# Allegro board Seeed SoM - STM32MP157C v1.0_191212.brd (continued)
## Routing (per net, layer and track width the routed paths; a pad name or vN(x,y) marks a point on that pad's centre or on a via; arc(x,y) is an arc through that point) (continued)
VDD_CORE: length 25.4
  TOP w0.152: 29.11,27.07 29.28,27.23 U2.5
  TOP w0.203: U3.1D1 U3.1C2 U3.1D3 13.27,12.41 v1(13.39,12.41) 13.73,12.07 U3.1E4 ; U3.1D1 U3.1E2 ; U3.1D1 11.41,12.98 v1(11.41,13.35) ; U3.1C4 v1(13.46,13.52) ; U3.1A2 U3.1B1 11.71,13.97 v1(11.71,14.29) ; U3.1F5 v1(14.13,11.56) ; U3.1F5 U3.1G6 15.11,10.65 v1(15.44,10.33) 15.68,10.09 U3.1H7 ; U3.1F5 U3.1E6 15.4,12.32 15.4,12.41 15.41,12.42 v1(15.41,12.44) 15.57,12.6 U3.1D7 ; U3.1B5 14.38,14.06 14.3,14.14 v1(14.3,14.16) 14.64,14.16 U3.1A6 ; U3.1D5 14.58,12.81 v1(14.58,12.82) 14.85,13.08 14.86,13.08 U3.1C6 ; v1(15.98,11.65) 15.98,11.6 U3.1F7 ; U3.1B3 v1(13.49,14.31) U3.1A4
  BOTTOM w0.203: C29.1 15.65,10.18 15.5,10.33 v1(15.44,10.33) ; v1(14.13,11.56) 14.13,11.59 C31.1 ; C28.1 11.49,13.24 11.43,13.3 11.43,13.32 v1(11.41,13.35) 11.43,13.37 11.43,13.4 11.46,13.43 11.46,13.47 11.48,13.49 C30.1 11.48,14.09 11.68,14.29 v1(11.71,14.29)
  BOTTOM w0.254: 13.97,13.85 C33.1 ; v1(13.39,12.41) 13.74,12.07 C31.1 ; 13.8,13.86 v1(13.46,13.52)
  BOTTOM w0.305: C33.1 13.52,14.31 v1(13.49,14.31) 13.08,13.91 C32.1 13.13,13.85 v1(13.46,13.52) ; C33.1 14,13.86 v1(14.3,14.16) ; C33.1 13.8,13.86 ; v1(15.98,11.65) 16.02,11.69 C120.1 15.95,12 15.83,12 15.81,11.98 15.49,11.98
  BOTTOM w0.381: v1(14.58,12.82) 14.86,13.09 C34.1 14.98,13.03 14.98,12.81 15.25,12.54 15.31,12.54 v1(15.41,12.44) 15.28,12.31 C35.1 15.49,11.98 15.83,11.65 v1(15.98,11.65) ; C121.1 14.8,14.66 v1(14.3,14.16)
  vias: v1(27.97,26.31) v1(27.97,25.94) v1(28.48,26.31) v1(28.48,25.92)
VDD_USB: length 20.2
  TOP w0.089: U3.AA17 16.63,7.21 16.13,7.21 U3.AA15 v2(15.88,7.46)
  TOP w0.152: 25.81,30.12 26.14,30.44 U2.39
  TOP w0.381: 25.81,30.12 25.81,29.86 v1(25.23,29.28) C207.1
  GND02 w0.254: v1(16.59,4.36) 15.88,5.07 v2(15.88,7.46)
  LAYER_3 w0.356: v1(25.79,3.83) 25.79,3.14 25.2,2.56 22.89,2.56 20.25,5.2 17.43,5.2 v1(16.59,4.36)
  BOTTOM w0.254: v1(16.59,4.36) 16.97,3.98 C52.1
VDDA: length 34.8
  TOP w0.203: 33.66,31.32 33.59,31.24 U2.20
  TOP w0.356: v1(35.95,31.79) 34.98,31.79 34.73,31.54 C206.1
  TOP w0.381: C206.1 34.24,31.21 34.13,31.32 33.66,31.32
  LAYER_3 w0.356: v1(16.92,1.32) 17.59,0.65 v1(25.43,0.65)
  LAYER_5 w0.356: 27.97,5.6 27.97,3.19 v1(25.43,0.65) ; v1(16.92,1.32) 16.26,1.32 15.84,1.74 15.84,1.86 15.3,2.4 v1(10.8,2.4) ; 34.07,23.26 34.07,29.23 35.95,31.11 v1(35.95,31.79)
  BOTTOM w0.381: v1(10.8,2.4) 10.8,2.61 R93.1
VDDQ_DDR: length 56.8
  TOP w0.152: 31.14,26.94 30.87,27.21 U2.9
  TOP w0.203: U3.1G8 16.58,10.65 v1(16.6,10.63) ; U3.1H9 U3.1J8 16.33,9.08 v1(16.26,9.01) ; U3.1E8 16.69,11.6 v1(16.69,11.56) 16.95,11.3 U3.1F9 ; U3.1D9 U3.1C8 U3.1B9 16.98,14.05 v1(16.82,14.21) 16.48,14.55 U3.1A8 v1(15.96,14.18) U3.1B7
  TOP w0.305: U6.R1 v3(24.3,15.4) ; U6.R9 v3(24.27,8.23)
  TOP w0.356: v3(28.27,9.03) U6.K8 ; v3(36.28,9.03) U6.A8 ; v3(25.87,8.23) U6.N9 ; v3(32.28,15.43) U6.F1 ; v3(33.88,14.63) U6.D2 ; v3(35.48,14.63) U6.B2 ; v3(25.87,15.43) U6.N1 ; v3(33.08,8.23) U6.E9 ; U6.A1 36.07,15.22 36.07,15.72 v3(35.54,16.25) ; v3(31.48,9.82) U6.G7 ; v3(34.68,15.43) U6.C1 ; v3(30.68,14.63) U6.H2 ; v3(28.27,14.63) U6.K2 ; v3(30.68,8.23) U6.H9 ; v3(33.88,8.23) U6.D9 ; v3(34.68,8.23) U6.C9
  TOP w0.381: R102.2 v1(25.15,17.97) C80.1 ; C148.1 28.86,5.78 v1(29.01,5.93) ; v1(35.74,5.96) 35.72,5.93 C153.1 C152.1 ; C157.1 C156.1 ; C156.1 34.45,17.62 34.68,17.39 v1(34.68,17.29) ; C156.1 C155.1 ; C152.1 v1(34.7,5.93) ; C152.1 C151.1 C150.1 v1(32.31,5.52) C149.1 ; v1(24.45,5.52) C81.1 C147.1 v1(25.94,5.91) ; C155.1 v1(35.46,17.36) ; C155.1 C154.1 ; C82.1 v1(28.86,17.43)
  BOTTOM w0.203: C44.1 16.6,10.46 v1(16.6,10.63) 16.77,10.8 C42.1 16.77,11.48 v1(16.69,11.56) ; v1(16.82,14.21) 16.82,14.05 C43.1 16.37,13.77 v1(15.96,14.18) 16.26,14.18 16.3,14.21 v1(16.82,14.21)
  BOTTOM w0.381: v1(34.75,6.57) C79.1 v1(35.74,5.96) ; v1(27.13,3.83) 27.13,2.89 26.52,2.28 22.43,2.28 20.65,4.05 20.65,6.04 19.05,7.64 C132.1 C45.1 16.42,8.85 v1(16.26,9.01) ; v1(34.68,17.29) 34.68,17.92 34.95,18.19 C162.1 35.64,17.54 v1(35.46,17.36)
  vias: v1(31.58,24.07) v1(31.6,23.69) v1(32.01,24.14) v1(32.01,23.71) v1(34.57,26.43) v1(34.95,26.43)
ADC1_INN1: length 41.6
  TOP w0.089: U3.U3 10.13,9.21 10.58,9.21 v1(10.76,9.03)
  LAYER_5 w0.102: v1(14.25,36.59) 14.15,36.69 14.15,37.07 13.8,37.43 7.07,37.43 6.25,36.62 6.25,24.58 6.56,24.27 6.56,19.7 7.17,19.09 7.17,18.63 6.61,18.08 6.61,16.45 8.28,14.77 8.28,12.34 9.17,11.45 9.17,9.9 10.04,9.04 10.43,9.08 10.53,9 v1(10.76,9.03)
  BOTTOM w0.095: J4.37 14.22,35.76 14.16,35.82 14.16,36.5 v1(14.25,36.59)
ADC1_INP1: length 41.6
  TOP w0.089: v1(10.7,9.51) 10.67,9.51 10.61,9.45 U3.U4
  LAYER_5 w0.102: v1(13.72,36.57) 13.85,36.69 13.85,36.95 13.67,37.13 7.19,37.13 6.56,36.49 6.56,35.55 6.66,35.45 6.94,35.45 7.04,35.35 7.04,35.14 6.94,35.04 6.66,35.04 6.56,34.94 6.56,34.74 6.66,34.64 6.94,34.64 7.04,34.53 7.04,34.33 6.94,34.23 6.66,34.23 6.56,34.13 6.56,33.9 6.66,33.8 6.94,33.8 7.04,33.7 7.04,33.5 6.94,33.39 6.66,33.39 6.56,33.29 6.56,24.7 6.86,24.4 6.86,19.83 7.47,19.22 7.47,18.51 6.91,17.95 6.91,16.58 8.59,14.9 8.59,12.46 9.48,11.57 9.48,10.03 10.15,9.36 10.39,9.38 10.48,9.49 v1(10.7,9.51)
  BOTTOM w0.095: v1(13.72,36.57) 13.77,36.57 13.88,36.46 13.88,35.82 13.82,35.76 J4.39
ADC2_INP2: length 43.8
  TOP w0.089: U3.Y5 10.79,8.05 10.79,8.13 v1(10.7,8.22)
  LAYER_3 w0.089: v1(15.24,37.05) 12.96,37.05 12.78,37.22 6.83,37.22 6.81,37.2 5.92,37.2 v1(5.21,36.49)
  LAYER_5 w0.089: v1(10.7,8.22) 10.45,8.22 10.41,8.26 9.97,8.26 8.77,9.46 8.77,11.27 8.01,12.03 8.01,14.65 6.32,16.34 6.32,17.77 5.8,18.29 5.8,22.52 5.29,23.03 5.29,26.46 4.83,26.91 4.83,31.92 5.21,32.3 v1(5.21,36.49)
  BOTTOM w0.089: J4.33 15.02,36.03 15.04,36.05 15.04,36.76 15.07,36.8 15.07,36.87 v1(15.24,37.05)
AUDIO_RST: length 25.8
  TOP w0.089: U3.Y13 14.88,8.18 14.76,8.3 14.76,8.37 14.76,8.37 14.76,8.55 v1(14.51,8.8)
  LAYER_3 w0.089: v1(12.18,22.95) 12.44,22.69 13.17,22.69 14.03,21.83 14.86,21.83 17.25,19.44 17.25,19.37 v1(17.43,19.19)
  LAYER_5 w0.089: v1(17.43,19.19) 18.06,18.56 18.06,17.62 19.03,16.65 19.03,9.39 18.75,9.11 18.75,8.43 18.11,7.79 15.22,7.79 14.76,8.25 14.76,8.38 14.76,8.38 14.76,8.55 v1(14.51,8.8)
  BOTTOM w0.089: J2.23 12.23,22.65 12.18,22.7 v1(12.18,22.95)
BOOT0: length 19.1
  TOP w0.089: v1(8.11,11.45) U3.N1
  LAYER_5 w0.089: v1(4.53,21.77) 4.83,21.47 4.83,16.73 4.47,16.37 4.47,12.97 5.9,11.54 6.44,11.54 6.66,11.32 7.28,11.32 7.42,11.45 v1(8.11,11.45)
  BOTTOM w0.089: J2.5 8.63,21.27 8.46,21.1 5.2,21.1 v1(4.53,21.77)
BOOT1: length 16.7
  TOP w0.089: U3.N4 10.53,11.6 10.75,11.6 v1(10.81,11.53)
  LAYER_3 w0.089: v1(7.73,23.59) 8.7,22.61 8.7,22.54 v1(8.88,22.37)
  LAYER_5 w0.089: v1(7.73,23.59) 8.18,23.13 8.18,21.48 7.75,21.04 7.75,20.64 8.21,20.18 8.21,19.83 8.89,19.14 8.89,17.88 9.35,17.42 9.35,13.17 10.64,11.89 10.64,11.71 v1(10.81,11.53)
  BOTTOM w0.089: J2.7 9.03,22.18 8.88,22.34 v1(8.88,22.37)
BOOT2: length 21.8
  TOP w0.089: U3.M2 7.7,11.95 7.64,11.89 v1(7.61,11.89)
  LAYER_3 w0.089: v1(9.78,23) 8.87,23.92 6.09,23.92 5.86,23.69 5.24,23.69 5.15,23.78 v1(4.9,23.78)
  LAYER_5 w0.089: v1(7.61,11.89) 7.8,12.09 7.8,14.57 5.59,16.78 5.59,22.34 4.9,23.03 v1(4.9,23.78)
  BOTTOM w0.089: v1(9.78,23) 9.61,22.83 9.61,22.8 9.43,22.62 J2.9
BST_OUT: length 4.5
  TOP w0.152: v1(27.33,33.04) 27.59,33.04 27.68,32.95 U2.34 27.68,32.61 27.59,32.53
  TOP w0.381: R150.1 23.85,31.08 v1(23.65,30.88)
  BOTTOM w0.203: J4.21 v1(17.42,36.33) ; J4.17 18.22,36.05 v1(17.94,36.34) 17.94,36.03 17.82,35.92 J4.19
  vias: v1(23.65,31.26) v1(26.95,33.04)
DDR_A0: length 13.4
  TOP w0.089: U3.L20 18.02,12.45 v1(17.94,12.53)
  TOP w0.127: v3(25.87,13.83) U6.N3
  BOTTOM w0.127: R17.1 26.58,15.86 26.27,15.55 26.27,15.26 25.87,14.86 v3(25.87,13.83) 25.65,13.6 25.65,13.44 24.62,12.41 22.74,12.41 21.34,13.81 20.63,13.81 19.28,12.46 18.27,12.46 18.21,12.53 v1(17.94,12.53)
DDR_A1: length 13.1
  TOP w0.089: U3.P22 19.63,10.71 20.75,10.71
  TOP w0.127: v1(25.07,9.83) U6.P7 25.12,10.58 23.09,10.58 22.97,10.46 22.97,9.08 22.84,8.96 22.59,8.96 22.46,9.08 22.46,10.58 22.33,10.71 20.75,10.71
  BOTTOM w0.127: R18.1 26.32,8.06 26.3,8.07 26.3,8.44 26.12,8.63 25.71,8.63 25.51,8.83 25.51,9.39 v1(25.07,9.83)
DDR_A2: length 12
  TOP w0.089: U3.J20 18.12,13.45 18.11,13.45 18.06,13.45 v1(18.06,13.45)
  TOP w0.127: v3(25.07,13.83) U6.P3
  BOTTOM w0.089: 18.32,13.71 v1(18.06,13.45)
  BOTTOM w0.127: R19.1 25.68,15.76 25.48,15.55 25.48,14.23 v3(25.07,13.83) 25.07,13.27 24.52,12.72 22.84,12.72 21.52,14.04 18.65,14.04 18.32,13.71
DDR_A3: length 13.5
  TOP w0.089: U3.K22 19.7,13.27 20.98,13.27 v1(21.19,13.48)
  TOP w0.127: U6.N2 26.64,13.86 v3(26.67,13.86)
  BOTTOM w0.127: R20.1 27.48,16.14 27.11,15.77 27.11,15.28 26.88,15.06 26.59,15.06 26.31,14.78 26.31,14.23 v3(26.67,13.86) 26.27,13.46 26.27,13.28 26.33,13.22 26.33,13.04 26.15,12.86 25.98,12.86 25.86,12.97 25.66,12.97 25.49,12.8 25.49,12.62 25.62,12.5 25.62,12.32 25.44,12.14 25.15,12.14 25.09,12.2 24.91,12.2 24.77,12.06 22.61,12.06 v1(21.19,13.48)
DDR_A4: length 11.6
  TOP w0.089: v1(17.33,8.8) 17.58,8.8 17.59,8.8 17.62,8.8 17.77,8.95 U3.V20
  TOP w0.127: v3(25.07,9.03) U6.P8
  LAYER_3 w0.089: v1(17.33,8.8) 17.53,8.6 17.53,8.58 17.82,8.3 18.17,8.3
  LAYER_3 w0.127: 18.17,8.3 22.13,8.3 22.48,8.65 24.7,8.65 v3(25.07,9.03)
  BOTTOM w0.127: v3(25.07,9.03) 25.07,8.8 25.44,8.44 25.44,7.81 25.43,7.79 R21.1
DDR_A5: length 13.5
  TOP w0.089: U3.H20 17.5,13.95 17.22,13.68 v1(17.22,13.61)
  TOP w0.127: v3(25.07,14.63) U6.P2
  BOTTOM w0.089: 18.17,14.11 18.09,14.04 17.65,14.04 17.56,13.94 17.53,13.94 17.35,13.76 17.35,13.73 v1(17.22,13.61)
  BOTTOM w0.127: 18.17,14.11 18.39,14.34 21.72,14.34 23.04,13.02 24.34,13.02 24.69,13.38 24.69,14.25 v3(25.07,14.63) 24.71,15 24.71,15.77 24.79,15.86 R22.1
DDR_A6: length 10.7
  TOP w0.089: v1(17.99,8.63) 18.21,8.63 U3.W20
  TOP w0.127: v3(24.27,9.03) U6.R8
  LAYER_3 w0.127: v3(24.27,9.03) 23.96,9.03 23.89,8.96 22.19,8.96 21.99,8.75 21.68,8.75 21.48,8.96 21.25,8.96 21.12,8.83 21.12,8.73 20.99,8.6 20.74,8.6 20.61,8.73 20.61,8.83 20.49,8.96 20.23,8.96 20.1,8.83 20.1,8.73 19.98,8.6 19.72,8.6 19.6,8.73 19.6,8.83 19.47,8.96 19.22,8.96 19.09,8.83 19.09,8.73 18.96,8.6 18.71,8.6 18.58,8.73 18.58,8.83 18.45,8.96 18.27,8.96 18.18,8.87 18.18,8.82 v1(17.99,8.63)
  BOTTOM w0.127: v3(24.27,9.03) 23.88,8.64 23.88,7.68 23.71,7.51 R23.1
DDR_A7: length 12
  TOP w0.089: U3.E20 18.14,15.45 18.09,15.41 18.07,15.41 v1(18.07,15.4)
  TOP w0.127: v3(24.27,14.63) U6.R2
  LAYER_3 w0.127: v3(24.27,14.63) 23.54,14.63 22.05,16.12 22.05,17.05 v1(22.42,17.42)
  BOTTOM w0.127: v3(24.27,14.63) 23.91,15 R24.1 ; v1(18.07,15.4) 19.43,15.4 21.44,17.42 v1(22.42,17.42)
DDR_A8: length 11.2
  TOP w0.089: v1(17.33,8.35) 17.63,8.35 17.7,8.27 18.06,8.27 U3.Y20
  TOP w0.127: U6.T8 23.01,8.57 23.01,8.42 v3(22.79,8.19)
  LAYER_3 w0.127: v3(22.79,8.19) 22.25,7.66 21.42,7.66 21.29,7.79 21.29,7.89 21.17,8.02 20.91,8.02 20.79,7.89 20.79,7.69 20.66,7.56 20.41,7.56 20.28,7.69 20.28,7.89 20.15,8.02 19.92,8.02 19.8,7.89 19.8,7.66 19.67,7.53 19.41,7.53 19.29,7.66 19.29,7.86 19.14,8.02 18.88,8.02 18.75,7.89 18.75,7.79 18.63,7.66 18.01,7.66 v1(17.33,8.35)
  BOTTOM w0.127: R25.1 22.76,7.79 22.79,7.82 v3(22.79,8.19)
DDR_A9: length 11.8
  TOP w0.127: v1(18.04,14.57) 18.16,14.45 U3.G20 ; v3(24.27,13.83) U6.R3
  BOTTOM w0.127: v1(18.04,14.57) 18.04,14.6 18.22,14.77 19.82,14.77 20.05,15 22.2,15 22.99,14.21 22.99,13.55 23.27,13.27 24.04,13.27 24.27,13.51 v3(24.27,13.83) 23.91,14.2 23.91,14.47 22.97,15.41 R26.1
DDR_A10: length 13.9
  TOP w0.089: 20.83,10.45 U3.R22
  TOP w0.127: v1(22,9.9) 21.44,10.45 20.83,10.45 ; v3(27.47,9.83) U6.L7
  LAYER_3 w0.127: v1(22,9.9) 22.48,9.9 23.19,10.61 26.69,10.61 v3(27.47,9.83)
  BOTTOM w0.127: v3(27.47,9.83) 29.34,9.83 29.8,9.36 29.8,8.03 29.87,7.96 R27.1
DDR_A11: length 11.8
  TOP w0.089: U3.R20 18.18,10.25 17.78,10.25 17.7,10.17 17.7,10.09 v1(17.53,9.92)
  TOP w0.127: v3(24.27,9.83) U6.R7
  LAYER_3 w0.127: v1(17.53,9.92) 17.86,10.25 18.8,10.25 19.49,9.57 22.61,9.57 23.27,10.23 23.87,10.23 v3(24.27,9.83)
  BOTTOM w0.127: v3(24.27,9.83) 24.69,9.41 24.69,7.94 24.54,7.79 R28.1
DDR_A12: length 12.9
  TOP w0.089: U3.P23 20.87,10.95
  TOP w0.127: v1(25.89,9.84) U6.N7 25.91,10.59 25.91,11.15 25.82,11.24 25.57,11.24 25.48,11.15 25.48,11.01 25.3,10.84 24.69,10.84 24.41,11.12 24.12,11.12 23.91,10.9 23.46,10.9 23.12,11.24 22.86,11.24 22.58,10.95 20.87,10.95
  BOTTOM w0.127: v1(25.89,9.84) 26.29,9.44 26.83,9.44 27.66,8.6 28.43,8.6 28.6,8.42 28.6,7.96 28.16,7.51 R29.1
DDR_A13: length 9.2
  TOP w0.089: v1(17.66,14.88) 17.74,14.95 U3.F20
  TOP w0.127: v3(23.47,13.83) U6.T3
  BOTTOM w0.127: v1(17.66,14.88) 17.85,15.06 19.62,15.06 20.71,16.15 21.66,16.15 21.66,16.14 R30.1 22.06,16.14 22.64,15.57 22.64,15.33 23.47,14.49 v3(23.47,13.83)
DDR_A14: length 11.1
  TOP w0.089: U3.R21 18.63,10.71 18.24,10.71 18.01,10.48 17.83,10.48 17.79,10.52 17.63,10.52 v1(17.46,10.7)
  TOP w0.127: v3(23.47,9.83) U6.T7
  BOTTOM w0.089: v1(17.46,10.7) 17.51,10.65 17.51,10.57 17.59,10.48 18.45,10.48
  BOTTOM w0.127: v3(23.47,9.83) 22.38,8.73 22.38,7.96 21.94,7.51 R31.1 21.81,7.51 18.84,10.48 18.45,10.48
DDR_A15: length 15.3
  TOP w0.089: v1(17.92,10.83) 17.95,10.86 18.09,10.86 18.18,10.95 U3.P20
  TOP w0.127: U6.M7 v1(26.67,9.82)
  BOTTOM w0.127: R119.1 29.05,7.51 29.49,7.96 29.49,9.24 29.29,9.44 27.32,9.44 26.93,9.82 v1(26.67,9.82) 26.24,10.25 19.59,10.25 19.01,10.83 18.19,10.83 v1(17.92,10.83)
DDR_BA0: length 12.9
  TOP w0.089: U3.L23 20.29,12.45 20.5,12.67 20.81,12.67 v1(20.92,12.78)
  TOP w0.127: v3(26.67,14.63) U6.M2
  BOTTOM w0.127: R32.1 28.42,16.14 27.13,14.85 26.9,14.85 v3(26.67,14.63) 27.04,14.26 27.04,13.35 25.4,11.7 22.48,11.7 21.39,12.79 21.1,12.79 21.09,12.78 v1(20.92,12.78)
DDR_BA1: length 12
  TOP w0.089: v1(17.99,9.3) 18.23,9.3 U3.U20
  TOP w0.127: v3(25.87,9.03) U6.N8
  LAYER_3 w0.127: v1(17.99,9.3) 24.03,9.3 24.19,9.46 25.44,9.46 v3(25.87,9.03)
  BOTTOM w0.127: v3(25.87,9.03) 26.19,9.03 26.57,8.65 27.13,8.65 27.44,8.34 27.44,7.68 27.27,7.51 R33.1
DDR_BA2: length 23.9
  TOP w0.089: v1(17.47,11.58) 17.65,11.75 17.73,11.75 17.78,11.81 18.04,11.81 18.14,11.71 18.63,11.71 U3.M21
  TOP w0.127: U6.M3 27.07,12.73 27.24,12.56 27.79,12.56 28.24,13.01 v3(29.09,13.01)
  LAYER_3 w0.127: v3(29.09,13.01) 28.77,13.01 27.41,11.65 20.45,11.65 20.2,11.9 17.8,11.9 v1(17.47,11.58)
  BOTTOM w0.127: R34.1 33.88,16.14 33.48,15.75 33.48,14.44 32.05,13.01 v3(29.09,13.01)
DDR_CASN: length 19
  TOP w0.089: v1(17.91,11.5) 17.95,11.45 U3.N20
  TOP w0.127: v3(28.27,13.83) U6.K3
  BOTTOM w0.127: v1(17.91,11.5) 19.18,11.5 19.87,10.81 26.04,10.81 28.27,13.05 v3(28.27,13.83) 28.5,13.83 28.93,14.26 31.67,14.26 31.86,14.44 31.86,15.6 32.11,15.86 R36.1
DDR_CKE: length 20.1
  TOP w0.089: v1(18.02,9.92) 18.09,9.92 18.12,9.95 U3.T20
  TOP w0.127: R14.2 R38.1 29.87,5.99 28.25,7.61 v1(28.25,8.2) U6.K9
  LAYER_3 w0.127: v1(28.25,8.2) 27.86,8.59 25.72,8.59 25.51,8.38 25.51,7.89 25.3,7.69 22.94,7.69 22.33,7.08 v1(22.33,5.88)
  BOTTOM w0.127: v1(18.02,9.92) 18.85,9.92 21.26,7.51 21.26,6.44 21.82,5.88 v1(22.33,5.88)
DDR_CLK: length 32.9
  TOP w0.089: 21.49,12.06 21.14,11.7 19.63,11.7 U3.N22
  TOP w0.095: U6.J7 29.21,10.49 29.21,10.67 29.36,10.82 33.94,10.82 34.2,11.08 34.2,11.69 33.94,11.95 33.28,11.95 33.18,12.04 33.18,12.3 32.92,12.56 32.5,12.56 32.24,12.3 32.24,12.04 32.15,11.95 30.66,11.95 30.54,12.07 30.54,12.81 30.24,13.1 29.78,13.1 29.47,12.79 29.47,12.3 29.38,12.21 28.69,12.21 28.35,11.86 28.35,11.21 28.25,11.12 28.06,11.12 27.96,11.21 27.96,11.75 27.71,12 27.28,12 27.02,11.75 27.02,11.21 26.93,11.12 26.69,11.12 26.59,11.21 26.59,12.66 26.26,13 25.49,13 25.23,12.73 25.23,11.89 25.1,11.76 24.87,11.76 24.78,11.86 24.78,12.74 24.52,13 24.1,13 23.84,12.74 23.84,11.86 23.74,11.76 23.55,11.76 23.46,11.86 23.46,12.79 23.2,13.05 22.78,13.05 22.52,12.79 22.52,11.96 22.42,11.87 22.06,11.87 21.85,12.08 R16.2 21.52,12.08 21.49,12.06
DDR_CLKN: length 32.9
  TOP w0.089: 21.57,11.34 21.39,11.52 21.25,11.52 21.16,11.44 21.16,11.36 21.07,11.27 20.95,11.27 20.86,11.36 20.86,11.43 20.77,11.52 20.64,11.52 20.55,11.43 20.55,11.33 20.49,11.27 20.32,11.27 20.25,11.34 20.25,11.44 20.16,11.52 19.95,11.52 U3.N23
  TOP w0.095: 21.57,11.34 21.6,11.32 R16.1 21.9,11.32 22.17,11.59 22.54,11.59 22.8,11.84 22.8,12.67 22.89,12.77 23.08,12.77 23.18,12.67 23.18,11.74 23.44,11.48 23.86,11.48 24.12,11.74 24.12,12.62 24.21,12.72 24.4,12.72 24.5,12.62 24.5,11.74 24.76,11.48 25.21,11.48 25.51,11.78 25.51,12.61 25.61,12.72 26.14,12.72 26.31,12.54 26.31,11.1 26.57,10.84 27.04,10.84 27.3,11.1 27.3,11.63 27.4,11.73 27.59,11.73 27.68,11.63 27.68,11.1 27.94,10.84 28.37,10.84 28.62,11.1 28.62,11.74 28.81,11.93 29.49,11.93 29.75,12.19 29.75,12.67 29.9,12.82 30.13,12.82 30.26,12.69 30.26,11.95 30.54,11.67 32.26,11.67 32.52,11.93 32.52,12.19 32.62,12.28 32.81,12.28 32.9,12.19 32.9,11.93 33.16,11.67 33.83,11.67 33.92,11.57 33.92,11.19 33.83,11.1 29.94,11.1 29.85,11.19 29.85,11.34 29.75,11.45 29.52,11.45 29.42,11.34 29.42,11.17 29.34,11.1 29.24,11.1 28.94,10.79 28.94,10.49 U6.K7
DDR_CSN: length 14.9
  TOP w0.089: U3.M22 19.57,11.95 19.59,11.93 20.68,11.93 20.83,12.08 v1(21.01,12.08)
  TOP w0.127: v3(27.47,14.63) U6.L2
  BOTTOM w0.127: v1(21.01,12.08) 21.59,12.08 22.28,11.4 25.63,11.4 27.06,12.82 27.06,13.06 27.12,13.13 27.12,13.14 27.47,13.49 v3(27.47,14.63) 27.91,15.06 28.59,15.06 29.09,15.56 30.1,15.56 30.34,15.79 R37.1
DDR_D0: length 40
  TOP w0.089: U3.E22 19.63,15.21 20.1,15.21 20.73,15.84
  TOP w0.127: v1(34.5,21.15) 35.69,21.15 36.83,20.01 36.83,14.49 36.57,14.23 U6.A2 ; v1(21.7,20.44) 20.98,20.44 20.73,20.18 20.73,15.84
  LAYER_3 w0.127: v1(34.5,21.15) 33.91,21.73 33.44,21.73 33.31,21.61 33.31,21.35 33.19,21.23 32.93,21.23 32.81,21.35 32.81,21.61 32.68,21.73 31.5,21.73 31.37,21.61 31.37,21.15 31.24,21.02 30.99,21.02 30.86,21.15 30.86,21.61 30.74,21.73 30.48,21.73 30.36,21.61 30.36,21.15 30.23,21.02 29.97,21.02 29.85,21.15 29.85,21.61 29.72,21.73 29.47,21.73 29.34,21.61 29.34,21.15 29.21,21.02 28.96,21.02 28.83,21.15 28.83,21.61 28.7,21.73 28.45,21.73 28.32,21.61 28.32,21.15 28.2,21.02 27.94,21.02 27.82,21.15 27.82,21.61 27.69,21.73 27.43,21.73 27.31,21.61 27.31,21.15 27.18,21.02 26.93,21.02 26.8,21.15 26.8,21.61 26.67,21.73 26.42,21.73 26.29,21.61 26.29,21.15 26.16,21.02 25.91,21.02 25.78,21.15 25.78,21.61 25.66,21.73 25.4,21.73 25.28,21.61 25.28,21.15 25.15,21.02 24.89,21.02 24.77,21.15 24.77,21.61 24.64,21.73 24.39,21.73 24.26,21.61 24.26,21.15 24.13,21.02 23.88,21.02 23.75,21.15 23.75,21.61 23.62,21.73 22.72,21.73 21.7,20.7 v1(21.7,20.44)
DDR_D1: length 39.9
  TOP w0.089: U3.F22 20.2,14.95 21.09,15.84
  TOP w0.127: v3(34.68,13.83) U6.C3 ; 21.09,15.84 21.09,19.88 21.11,19.9 v1(21.11,20.01)
  LAYER_3 w0.127: v3(34.68,13.83) 35.09,14.24 35.69,14.24 35.92,14.47 35.92,18.19 34.51,19.6 29.85,19.6 29.72,19.73 29.72,20.49 29.62,20.59 29.33,20.59 29.2,20.46 29.2,19.78 29.07,19.65 28.82,19.65 28.69,19.78 28.69,20.46 28.57,20.59 28.31,20.59 28.18,20.46 28.18,19.78 28.06,19.65 27.8,19.65 27.68,19.78 27.68,20.46 27.55,20.59 27.26,20.59 27.13,20.46 27.13,19.78 26.98,19.62 26.76,19.62 26.63,19.75 26.63,20.5 26.5,20.63 26.25,20.63 26.12,20.5 26.12,19.76 25.99,19.62 25.74,19.62 25.61,19.75 25.61,20.49 25.49,20.62 25.23,20.62 25.11,20.49 25.11,19.75 24.98,19.62 24.73,19.62 24.6,19.75 24.6,20.41 24.47,20.54 24.03,20.54 23.9,20.41 23.9,19.52 23.78,19.4 23.52,19.4 23.4,19.52 23.4,20.41 23.27,20.54 22.61,20.54 22.48,20.41 22.48,19.52 22.33,19.37 22.03,19.37 21.9,19.5 21.9,19.88 21.77,20.01 v1(21.11,20.01)
DDR_D2: length 39.7
  TOP w0.089: U3.H21 18.63,14.2 17.73,14.2 v1(17.59,14.34)
  TOP w0.127: v3(36.36,10.71) U6.A7
  LAYER_3 w0.127: v1(17.59,14.34) 17.78,14.15 18.08,14.15 18.17,14.24 18.18,14.24 19.33,15.4 19.33,19.36 22.47,22.5 34.8,22.5 37.39,19.9 37.39,12.19 37.27,12.06 36.96,12.06 36.83,11.93 36.83,11.68 36.96,11.55 37.27,11.55 37.39,11.42 37.39,11.04 37.06,10.71 v3(36.36,10.71)
DDR_D3: length 39.9
  TOP w0.089: U3.E21 19.13,15.7 20.11,15.7
  TOP w0.127: v3(34.68,14.63) U6.C2 ; v1(20.25,17.21) 20.25,15.84 20.11,15.7
  LAYER_3 w0.127: v3(34.68,14.63) 35.08,15.03 35.08,16.07 34.95,16.2 34.32,16.2 34.19,16.32 34.19,16.65 34.29,16.75 34.85,16.75 35.06,16.96 35.06,18.51 34.88,18.69 34.55,18.69 34.42,18.56 34.42,17.5 34.21,17.29 33.74,17.29 33.56,17.47 33.56,18.79 33.1,19.24 31.06,19.24 30.93,19.12 30.93,18.89 30.8,18.76 30.55,18.76 30.42,18.89 30.42,19.12 30.29,19.24 29.98,19.24 29.8,19.07 29.8,18.86 29.67,18.74 28.68,18.74 28.53,18.89 28.53,19.02 28.38,19.17 27.84,19.17 27.69,19.02 27.69,18.81 27.56,18.69 25.27,18.69 24.99,18.96 21.72,18.96 21.54,18.78 21.54,15.05 21.41,14.93 21.16,14.93 21.03,15.05 21.03,15.28 20.88,15.43 20.2,15.43 20.07,15.56 20.07,15.81 20.2,15.94 20.9,15.94 21.03,16.07 21.03,16.3 20.9,16.42 20.65,16.42 20.53,16.55 20.53,16.81 20.65,16.93 20.9,16.93 21.03,17.06 21.03,18.81 20.9,18.94 20.54,18.94 20.25,18.65 v1(20.25,17.21)
DDR_D4: length 39.9
  TOP w0.089: U3.J21 18.63,13.7 18.25,13.7 18.19,13.76 17.73,13.76 17.61,13.65 v1(17.61,13.4)
  TOP w0.127: v3(35.48,9.03) U6.B8
  LAYER_3 w0.127: v1(17.61,13.4) 17.61,13.67 17.86,13.91 18.27,13.91 19.69,15.33 19.69,19.19 22.61,22.11 34.47,22.11 36.99,19.6 36.99,12.72 35.87,11.6 35.87,9.42 v3(35.48,9.03)
DDR_D5: length 40
  TOP w0.089: U3.J22 20.68,13.45 21.34,14.11
  TOP w0.127: 21.34,14.11 22.25,14.11 22.94,14.8 22.94,15.41 22.48,15.87 v1(22.48,16.45) ; v3(34.68,9.03) U6.C8
  LAYER_3 w0.127: v3(34.68,9.03) 34.31,9.39 34.31,10.83 34.18,10.96 33.23,10.96 33.1,11.09 33.1,11.34 33.23,11.47 34.18,11.47 34.31,11.59 34.31,11.85 34.18,11.97 33.23,11.97 33.1,12.1 33.1,12.36 33.23,12.48 34.18,12.48 34.31,12.61 34.31,15.65 33.14,16.82 33.14,17.07 33.01,17.2 32.75,17.2 32.62,17.32 32.62,17.58 32.75,17.7 33.01,17.7 33.14,17.83 33.14,18.11 32.87,18.38 32.48,18.38 32.35,18.51 32.35,18.81 32.22,18.94 31.97,18.94 31.84,18.81 31.84,18.51 31.72,18.38 31.25,18.38 31.13,18.25 31.13,18.1 31,17.97 30.75,17.97 30.62,18.1 30.62,18.25 30.49,18.38 30.24,18.38 30.11,18.25 30.11,18.1 29.98,17.97 29.73,17.97 29.6,18.1 29.6,18.25 29.48,18.38 29.22,18.38 29.1,18.25 29.1,18.1 28.97,17.97 28.71,17.97 28.59,18.1 28.59,18.25 28.46,18.38 26.47,18.38 26.35,18.25 26.35,17.54 26.22,17.42 25.97,17.42 25.84,17.54 25.84,18.25 25.71,18.38 24.82,18.38 24.7,18.25 24.7,18.08 24.57,17.95 24.31,17.95 24.16,18.1 24.16,18.43 24.04,18.56 23.76,18.56 23.64,18.43 23.64,18.2 23.51,18.08 23.26,18.08 23.13,18.2 23.13,18.43 23,18.56 22.43,18.56 22.31,18.43 22.31,18 22.43,17.87 22.62,17.87 22.75,17.74 22.75,17.28 22.48,17.01 v1(22.48,16.45)
DDR_D6: length 40
  TOP w0.089: 21.44,14.49 20.58,13.63 19.7,13.63 U3.H22
  TOP w0.127: v1(22.1,14.52) 21.9,14.72 21.67,14.72 21.44,14.49 ; v3(33.88,9.83) U6.D7
  LAYER_3 w0.127: v1(22.1,14.52) 19.69,14.52 19.54,14.37 19.54,14.08 19.66,13.95 19.83,13.95 19.96,13.83 19.96,12.77 20.08,12.64 20.34,12.64 20.47,12.77 20.47,13.78 20.64,13.95 22.13,13.95 22.25,13.83 22.25,13.57 22.13,13.44 21.65,13.44 21.52,13.32 21.52,12.84 21.8,12.56 26.73,12.56 26.93,12.77 26.93,13.17 26.8,13.3 26.45,13.3 26.31,13.44 26.31,15.76 26.43,15.89 27.1,15.89 27.22,15.76 27.22,15.46 27.35,15.33 27.6,15.33 27.73,15.46 27.73,15.76 27.86,15.89 28.94,15.89 29.06,15.76 29.06,15.54 29.19,15.41 29.44,15.41 29.57,15.54 29.57,15.76 29.7,15.89 29.95,15.89 30.08,15.76 30.08,15.54 30.21,15.41 30.46,15.41 30.59,15.54 30.59,15.76 30.71,15.89 32.47,15.89 32.67,15.69 32.67,13.78 32.54,13.66 32.34,13.66 32.21,13.53 32.21,13.28 32.34,13.15 32.54,13.15 32.67,13.02 32.67,12.59 32.52,12.43 32.34,12.43 32.21,12.31 32.21,12.05 32.34,11.93 32.55,11.93 32.68,11.8 32.68,11.55 32.55,11.42 32.34,11.42 32.21,11.29 32.21,11.04 32.34,10.91 32.55,10.91 32.68,10.78 32.68,10.59 32.88,10.39 33.75,10.39 33.88,10.27 v3(33.88,9.83)
DDR_D7: length 40.5
  TOP w0.089: U3.G21 19.13,14.7 20.33,14.7 21.39,15.76
  TOP w0.127: 21.39,15.76 21.39,19.52 23.37,21.5 33.08,21.5 33.21,21.63 33.21,21.96 33.33,22.09 33.59,22.09 33.71,21.96 33.71,21.63 33.84,21.5 34.07,21.5 34.2,21.63 34.2,21.96 34.32,22.09 34.58,22.09 34.7,21.96 34.7,21.65 34.83,21.52 35.09,21.52 35.21,21.65 35.21,21.96 35.34,22.09 35.59,22.09 35.72,21.96 35.72,21.65 35.85,21.52 36.06,21.52 37.24,20.34 37.24,11.67 36.99,11.42 36.15,11.42 35.88,11.69 35.88,12.2 35.75,12.33 34.85,12.33 34.73,12.46 34.73,12.71 34.85,12.84 35.75,12.84 35.88,12.97 U6.A3
DDR_D8: length 29.2
  TOP w0.089: U3.T21 18.63,9.71 18.28,9.71 18.18,9.61 17.84,9.61 17.73,9.5 17.6,9.5 v1(17.57,9.47)
  TOP w0.127: v3(32.28,14.63) U6.F2
  LAYER_3 w0.127: v3(32.28,14.63) 31.88,15.03 30.23,15.03 29.87,14.67 29.87,13.27 27.64,11.04 27.19,11.04 26.93,11.29 26.68,11.29 26.42,11.04 26.17,11.04 25.92,11.29 25.66,11.29 25.41,11.04 25.15,11.04 24.9,11.29 24.65,11.29 24.39,11.04 24.14,11.04 23.88,11.29 23.63,11.29 23.38,11.04 23.12,11.04 22.56,10.48 22.29,10.48 22.17,10.61 22.17,11.12 22.04,11.24 21.81,11.24 21.68,11.12 21.68,10.15 21.56,10.02 21.3,10.02 21.17,10.15 21.17,11.09 21.02,11.24 20.79,11.24 20.67,11.12 20.67,10.15 20.54,10.02 20.29,10.02 20.16,10.15 20.16,11.09 20.01,11.24 19.75,11.24 19.63,11.12 19.63,10.68 19.5,10.56 19.24,10.56 19.12,10.68 19.12,11.37 18.99,11.5 18.74,11.5 18.61,11.37 18.61,10.61 18.48,10.48 17.71,10.48 17.7,10.47 17.48,10.25 17.32,10.25 17.1,10.03 17.1,9.59 17.22,9.47 v1(17.57,9.47)
DDR_D9: length 29.4
  TOP w0.089: 21.37,5.91 21.37,8.09 20.25,9.21 19.13,9.21 U3.U21
  TOP w0.127: v1(33.46,3.88) 29.34,3.88 28.78,3.32 23.27,3.32 21.37,5.22 21.37,5.91 ; v3(33.05,13.05) U6.E3
  BOTTOM w0.127: v1(33.46,3.88) 33.46,9.24 33.25,9.44 32.94,9.44 32.71,9.67 32.71,10.26 33.05,10.61 v3(33.05,13.05)
DDR_D10: length 29.3
  TOP w0.089: 22.59,7.84 22.43,7.99 22.43,8.55 20.78,10.2 19.63,10.2 U3.T22
  TOP w0.127: v1(23.75,6.19) 23.04,6.19 22.76,6.47 22.76,6.72 22.92,6.87 23.58,6.87 23.7,7 23.7,7.27 23.58,7.39 22.71,7.39 22.59,7.52 22.59,7.84 ; v3(31.48,14.63) U6.G2
  LAYER_3 w0.127: v1(23.75,6.19) 23.07,6.19 22.89,6.37 22.89,7.05 23.17,7.33 25.81,7.33 25.94,7.46 25.94,7.73 26.07,7.86 26.32,7.86 26.45,7.73 26.45,7.46 26.58,7.33 27.01,7.33 27.13,7.46 27.13,7.76 27.26,7.89 27.51,7.89 27.64,7.76 27.64,7.46 27.77,7.33 28.38,7.33 28.71,7.66 28.71,9.43 28.58,9.56 28.07,9.56 27.94,9.68 27.94,9.94 28.07,10.07 28.58,10.07 28.71,10.19 28.71,10.45 28.58,10.57 28.22,10.57 28.1,10.7 28.1,10.95 28.22,11.08 28.58,11.08 28.71,11.21 28.71,11.62 30.21,13.12 30.21,14.01 30.43,14.24 31.09,14.24 v3(31.48,14.63)
DDR_D11: length 29.3
  TOP w0.089: U3.W21 19.13,8.7 20.15,8.7 20.88,7.97 20.88,5.88
  TOP w0.127: v1(32.67,2.99) 29.49,2.99 29.05,2.54 23.21,2.54 20.88,4.87 20.88,5.88 ; v3(32.28,9.82) U6.F7
  BOTTOM w0.127: v1(32.67,2.99) 32.67,3.25 32.47,3.46 32.47,3.95 32.67,4.16 32.67,4.59 32.47,4.79 32.47,5.11 32.67,5.32 32.67,5.85 32.41,6.1 32.41,6.36 32.67,6.61 32.67,7.08 31.88,7.86 31.88,9.19 31.67,9.39 31.24,9.39 31.09,9.54 31.09,10.07 31.35,10.33 32.09,10.33 32.28,10.13 v3(32.28,9.82)
DDR_D12: length 29.3
  TOP w0.089: U3.W23 20.07,8.45 20.63,7.89 20.63,5.91
  TOP w0.127: v1(32.16,2.53) 31.88,2.53 31.75,2.4 31.75,2.12 31.62,2 31.37,2 31.24,2.12 31.24,2.4 31.12,2.53 30.86,2.53 30.73,2.4 30.73,2.12 30.61,2 30.35,2 30.23,2.12 30.23,2.4 30.1,2.53 29.67,2.53 29.27,2.12 28.16,2.12 28.03,2 28.03,1.84 27.9,1.72 27.65,1.72 27.52,1.84 27.52,2 27.39,2.12 27.14,2.12 27.01,2 27.01,1.84 26.89,1.72 26.63,1.72 26.51,1.84 26.51,2 26.38,2.12 26.23,2.12 26.1,2 26.1,1.84 25.97,1.72 25.72,1.72 25.59,1.84 25.59,2 25.46,2.12 25.21,2.12 25.08,2 25.08,1.84 24.96,1.72 24.7,1.72 24.58,1.84 24.58,2 24.45,2.12 24.19,2.12 24.07,2 24.07,1.84 23.94,1.72 23.69,1.72 23.56,1.84 23.56,2 23.43,2.12 23.14,2.12 20.63,4.64 20.63,5.91 ; U6.H8 v1(30.69,9.01)
  BOTTOM w0.127: v1(32.16,2.53) 31.95,2.75 31.95,5.81 31.82,5.93 31.65,5.93 31.53,6.06 31.53,6.32 31.65,6.44 31.82,6.44 31.95,6.57 31.95,6.96 31.04,7.86 31.04,8.66 v1(30.69,9.01)
DDR_D13: length 29.3
  TOP w0.089: U3.T23 20.67,9.95 22.23,8.4 22.23,7.89
  TOP w0.127: v1(23.73,5.6) 23.12,5.6 22.23,6.49 22.23,7.89 ; v3(30.68,13.83) U6.H3
  LAYER_3 w0.127: v3(30.68,13.83) 31.63,13.83 31.78,13.67 31.78,13.22 31.65,13.1 30.71,13.1 29.44,11.83 29.44,11.37 29.32,11.24 29.14,11.24 29.01,11.12 29.01,10.86 29.14,10.74 29.32,10.74 29.44,10.61 29.44,10.35 29.32,10.23 29.14,10.23 29.01,10.1 29.01,9.85 29.14,9.72 29.32,9.72 29.44,9.59 29.44,8.27 29.32,8.15 29.19,8.15 29.06,8.02 29.06,7.77 29.19,7.64 29.32,7.64 29.44,7.51 29.44,6.52 29.32,6.39 29.01,6.39 28.89,6.52 28.89,6.87 28.76,7 28.51,7 28.38,6.87 28.38,6.54 28.25,6.42 28.01,6.42 27.89,6.54 27.89,6.85 27.76,6.98 27.51,6.98 27.38,6.85 27.38,6.72 27.25,6.59 27,6.59 26.87,6.72 26.87,6.85 26.74,6.98 26.49,6.98 26.36,6.85 26.36,6.49 26.24,6.37 25.98,6.37 25.86,6.49 25.86,6.8 25.73,6.92 25.47,6.92 25.35,6.8 25.35,6.42 25.22,6.29 24.85,6.29 24.74,6.39 24.74,6.82 24.67,6.9 24.26,6.9 24.13,6.77 24.13,5.74 23.99,5.6 v1(23.73,5.6)
DDR_D14: length 29.2
  TOP w0.089: U3.W22 19.63,8.21 20.01,8.21 20.35,7.86 20.35,5.91
  TOP w0.127: v1(31.55,1.39) 30.24,1.39 30.12,1.51 30.12,1.62 29.99,1.74 29.74,1.74 29.61,1.62 29.61,1.51 29.48,1.39 29.23,1.39 29.1,1.51 29.1,1.62 28.97,1.74 28.72,1.74 28.59,1.62 28.59,1.51 28.47,1.39 23.4,1.39 20.35,4.44 20.35,5.91 ; v3(30.68,9.83) U6.H7
  BOTTOM w0.127: v3(30.68,9.83) 30.18,9.33 30.18,8.12 30.42,7.88 30.42,7.36 30.55,7.23 31.07,7.23 31.2,7.1 31.2,6.85 31.07,6.72 30.55,6.72 30.42,6.59 30.42,6.15 30.71,5.86 31.17,5.86 31.55,5.48 v1(31.55,1.39)
DDR_D15: length 29.3
  TOP w0.089: 20.13,5.9 20.13,7.56 19.98,7.71 19.13,7.71 U3.Y21
  TOP w0.127: 20.13,5.9 20.13,4.15 23.25,1.03 32.06,1.03 32.18,1.16 32.18,1.54 32.31,1.67 32.56,1.67 32.69,1.54 32.69,1.16 32.82,1.03 33.23,1.03 v1(33.43,1.24) ; v3(32.28,9.03) U6.F8
  BOTTOM w0.127: v1(33.43,1.24) 33.09,1.58 33.09,7.34 32.71,7.72 32.71,8.59 v3(32.28,9.03)
DDR_DQM0: length 39.9
  TOP w0.089: 20.58,13.95 U3.H23
  TOP w0.127: v1(22.23,15.33) 21.96,15.33 20.58,13.95 ; v3(33.88,13.83) U6.D3
  LAYER_3 w0.127: v1(22.23,15.33) 23.04,14.52 23.04,13.38 23.27,13.15 25.05,13.15 25.46,13.55 25.46,15.61 25.25,15.81 23.12,15.81 22.99,15.94 22.99,16.45 23.12,16.58 23.73,16.58 23.85,16.7 23.85,17.42 23.98,17.54 24.23,17.54 24.36,17.42 24.36,16.7 24.49,16.58 24.74,16.58 24.87,16.7 24.87,17.42 25,17.54 25.25,17.54 25.38,17.42 25.38,16.7 25.5,16.58 26.49,16.58 26.62,16.7 26.62,17.24 26.75,17.36 27,17.36 27.13,17.24 27.13,16.4 27.26,16.27 27.51,16.27 27.64,16.4 27.64,17.24 27.76,17.36 28.02,17.36 28.15,17.24 28.15,16.4 28.27,16.27 28.53,16.27 28.65,16.4 28.65,16.93 28.78,17.06 29.03,17.06 29.16,16.93 29.16,16.4 29.29,16.27 29.54,16.27 29.67,16.4 29.67,16.93 29.8,17.06 30.05,17.06 30.18,16.93 30.18,16.4 30.3,16.27 30.56,16.27 30.69,16.4 30.69,16.93 30.81,17.06 31.07,17.06 31.19,16.93 31.19,16.4 31.32,16.27 31.57,16.27 31.73,16.42 31.73,17.72 31.85,17.85 32.11,17.85 32.24,17.72 32.24,16.4 32.36,16.27 33.08,16.27 33.44,15.9 33.44,14.26 v3(33.88,13.83)
DDR_DQM1: length 29.4
  TOP w0.089: U3.V22 20.23,8.95 21.14,8.04 21.14,5.88
  TOP w0.127: v1(33.48,3.27) 33.29,3.46 29.48,3.46 28.96,2.94 23.22,2.94 21.14,5.02 21.14,5.88 ; v3(33.08,9.83) U6.E7
  BOTTOM w0.127: v3(33.08,9.83) 33.3,9.83 33.71,9.41 34.07,9.41 34.29,9.19 34.29,7.85 34.17,7.72 33.96,7.72 33.84,7.59 33.84,7.34 33.96,7.21 34.27,7.21 34.4,7.09 34.4,6.83 34.27,6.71 33.96,6.71 33.84,6.58 33.84,6.32 33.96,6.2 34.17,6.2 34.29,6.07 34.29,5.82 34.17,5.69 33.96,5.69 33.84,5.56 33.84,5.31 33.96,5.18 34.17,5.18 34.29,5.05 34.29,3.5 34.07,3.27 v1(33.48,3.27)
DDR_DQS0: length 40
  TOP w0.089: 22.1,15.87 22.1,15.79 20.52,14.21 19.63,14.21 U3.G22
  TOP w0.095: v1(31.96,20.06) 31.76,20.26 30.55,20.26 30.45,20.16 30.45,19.63 30.19,19.37 29.77,19.37 29.51,19.63 29.51,20.34 29.42,20.44 29.06,20.44 28.97,20.34 28.97,19.6 28.71,19.35 28.29,19.35 28.03,19.6 28.03,20.39 27.93,20.49 27.74,20.49 27.65,20.39 27.65,19.66 27.39,19.4 26.97,19.4 26.71,19.66 26.71,20.39 26.61,20.49 26.26,20.49 26.17,20.39 26.17,19.77 25.91,19.51 25.49,19.51 25.23,19.77 25.23,20.22 25.13,20.31 24.84,20.31 24.75,20.22 24.75,20.06 24.49,19.8 24.07,19.8 23.81,20.06 23.81,20.22 23.71,20.31 23.4,20.31 22.1,19.02 22.1,15.87 ; U6.C7 v3(34.68,9.83)
  LAYER_3 w0.102: v1(31.96,20.06) 32.14,20.25 34.89,20.25 36.28,18.86 36.28,13.53 35.48,12.73 35.33,12.73 35.22,12.84 35.08,12.84 34.94,12.7 34.94,12.55 35.05,12.44 35.05,12.3 34.92,12.18 34.92,10.07 v3(34.68,9.83)
DDR_DQS1: length 29.3
  TOP w0.089: U3.U22 19.63,9.7 20.6,9.7 20.69,9.61 20.69,9.58 21.92,8.34 21.92,7.52
  TOP w0.095: U6.F3 31.58,13.13 31.58,12.73 v1(31.77,12.54) ; v1(24.55,3.8) 24.35,4 24.35,4.52 23.86,5.02 22.7,5.02 21.92,5.8 21.92,7.52
  LAYER_3 w0.102: v1(31.77,12.54) 31.58,12.35 31.58,11.07 31.27,10.76 30.46,10.76 30.28,10.58 30.28,6.78 30.38,6.68 30.69,6.68 30.97,6.4 30.97,5.94 30.69,5.66 30.38,5.66 30.28,5.56 30.28,5.12 29.9,4.74 29.03,4.74 28.75,5.02 28.75,5.17 28.65,5.27 28.45,5.27 28.35,5.17 28.35,5.02 28.07,4.74 27.63,4.74 27.35,5.02 27.35,5.38 27.25,5.48 27.05,5.48 26.95,5.38 26.95,5.05 26.64,4.74 26.07,4.74 25.79,5.02 25.79,5.18 25.69,5.29 25.48,5.29 25.38,5.18 25.38,5.02 25.1,4.74 24.62,4.74 24.37,4.49 24.37,3.99 v1(24.55,3.8)
DDR_DQSN0: length 39.9
  TOP w0.089: 21.82,15.87 20.41,14.45 U3.G23
  TOP w0.095: 21.82,15.87 21.82,19.13 23.28,20.59 23.83,20.59 24.09,20.33 24.09,20.18 24.18,20.08 24.37,20.08 24.47,20.18 24.47,20.33 24.73,20.59 25.25,20.59 25.51,20.33 25.51,19.88 25.6,19.79 25.79,19.79 25.89,19.88 25.89,20.51 26.15,20.77 26.73,20.77 26.99,20.51 26.99,19.77 27.08,19.68 27.27,19.68 27.37,19.77 27.37,20.51 27.63,20.77 28.05,20.77 28.31,20.51 28.31,19.72 28.4,19.62 28.59,19.62 28.69,19.72 28.69,20.46 28.95,20.72 29.53,20.72 29.79,20.46 29.79,19.75 29.89,19.65 30.08,19.65 30.17,19.75 30.17,20.28 30.43,20.54 30.91,20.54 31.01,20.63 31.01,20.8 31.1,20.89 31.29,20.89 31.39,20.8 31.39,20.63 31.49,20.54 31.76,20.54 v1(31.96,20.74) ; U6.B7 v3(35.48,9.83)
  LAYER_3 w0.102: v3(35.48,9.83) 35.23,10.07 35.23,12.05 36.58,13.4 36.58,18.99 35.02,20.55 32.14,20.55 v1(31.96,20.74)
DDR_DQSN1: length 29.2
  TOP w0.089: U3.U23 20.56,9.45 21.65,8.37 21.65,7.64
  TOP w0.095: U6.G3 31.3,13.2 31.3,12.75 v1(31.08,12.54) ; v1(23.88,3.8) 24.07,4 24.07,4.41 23.74,4.74 23.47,4.74 23.37,4.65 23.37,4.28 23.25,4.16 23.08,4.16 22.99,4.25 22.99,4.65 22.89,4.74 22.59,4.74 21.65,5.68 21.65,7.64
  LAYER_3 w0.102: v1(31.08,12.54) 31.27,12.35 31.27,11.19 31.14,11.07 30.33,11.07 29.98,10.71 29.98,6.65 30.26,6.37 30.56,6.37 30.66,6.27 30.66,6.07 30.56,5.96 30.26,5.96 29.98,5.68 29.98,5.25 29.77,5.05 29.16,5.05 29.06,5.15 29.06,5.3 28.78,5.58 28.32,5.58 28.04,5.3 28.04,5.15 27.94,5.05 27.76,5.05 27.66,5.15 27.66,5.5 27.38,5.78 26.92,5.78 26.64,5.5 26.64,5.17 26.52,5.05 26.2,5.05 26.09,5.15 26.09,5.31 25.81,5.59 25.36,5.59 25.08,5.31 25.08,5.15 24.98,5.05 24.49,5.05 24.06,4.62 24.06,3.99 v1(23.88,3.8)
DDR_ODT: length 14.2
  TOP w0.089: U3.L22 19.73,12.11 20.3,12.11 20.66,12.46 v1(21.24,12.46)
  TOP w0.127: v3(28.27,15.43) U6.K1
  LAYER_3 w0.127: v1(21.24,12.46) 21.67,12.03 27.21,12.03 27.89,12.72 27.89,15.05 v3(28.27,15.43)
  BOTTOM w0.127: R40.1 29.09,16.14 28.6,15.65 28.5,15.65 v3(28.27,15.43)
DDR_RASN: length 21.5
  TOP w0.089: U3.N21 18.63,11.2 18.28,11.2 18.22,11.14 v1(17.58,11.14)
  TOP w0.127: v3(29.07,13.83) U6.J3
  BOTTOM w0.127: R35.1 32.67,15.76 32.67,14.37 31.73,13.43 U6.J3 v3(29.07,13.83) 28.63,13.38 28.63,12.94 26.22,10.53 19.71,10.53 19.08,11.17 17.64,11.17 17.62,11.14 v1(17.58,11.14)
DDR_RESETN: length 15.9
  TOP w0.089: U3.D20 18.14,15.72 17.99,15.72 17.98,15.71 17.93,15.71 17.78,15.56 v1(17.65,15.56)
  TOP w0.127: U6.T2 23.18,14.92 23.18,16.01 23.04,16.15 23.04,17.65 23.36,17.97 R15.1 23.49,17.97 24.01,18.5 24.06,18.5 24.3,18.74 R102.1 24.36,19.22 v1(24.29,19.29)
  BOTTOM w0.127: v1(24.29,19.29) 23.88,19.7 22.56,19.7 21.39,18.53 21.39,17.85 19.33,15.79 17.88,15.79 v1(17.65,15.56)
DDR_WEN: length 19.5
  TOP w0.089: v1(17.31,12.42) 17.31,12.17 17.48,12 17.76,12 17.76,12 18.15,12 18.2,11.95 U3.M20
  TOP w0.127: U6.L3 27.49,13.04 v3(27.49,12.98)
  BOTTOM w0.089: v1(17.31,12.42) 17.31,12.17 17.6,11.88 18.65,11.88
  BOTTOM w0.127: 18.65,11.88 19.23,11.88 20,11.12 25.81,11.12 27.26,12.57 27.26,12.76 v3(27.49,12.98) 27.79,13.29 27.79,13.94 28.07,14.21 28.43,14.21 28.71,14.49 28.71,14.82 29.09,15.21 30.38,15.21 30.99,15.82 30.99,15.97 31.16,16.14 R39.1
DSI_CK_N: length 13.5
  TOP w0.089: 16.67,18.43 16.38,18.14 U3.A16
  TOP w0.095: 16.67,18.43 16.67,21.1 16.79,21.22 18.31,21.22 18.57,21.48 18.57,21.93 18.31,22.19 18,22.19 17.9,22.29 17.9,22.45 17.81,22.55 17.62,22.55 17.52,22.45 17.52,22.29 17.43,22.19 16.81,22.19 16.72,22.29 16.72,23.28 16.9,23.46 17.39,23.46 17.49,23.36 17.49,23.2 v1(17.29,23)
  BOTTOM w0.095: J2.49 17.43,22.14 17.49,22.2 17.49,22.38 17.38,22.5 16.84,22.5 16.77,22.57 16.77,22.85 16.9,22.98 17.27,22.98 v1(17.29,23)
DSI_CK_P: length 13.6
  TOP w0.089: 16.39,18.43 16.39,18.4 16.1,18.11 16.1,17.23 U3.B16
  TOP w0.095: 16.39,18.43 16.39,21.21 16.67,21.5 18.2,21.5 18.29,21.6 18.29,21.82 18.2,21.91 16.69,21.91 16.44,22.17 16.44,23.4 16.78,23.74 17.51,23.74 17.77,23.48 17.77,23.2 v1(17.97,23)
  BOTTOM w0.095: J2.51 17.83,22.12 17.77,22.18 17.77,22.81 v1(17.97,23)
DSI_D0_N: length 13.6
  TOP w0.089: U3.B15 15.88,18.28 16.11,18.51 16.11,20.89 15.78,21.23 15.78,21.36
  TOP w0.095: 15.78,21.36 15.78,21.4 15.85,21.48 16.21,21.48 16.29,21.56 16.29,21.86 16.21,21.94 15.88,21.94 15.78,22.04 15.78,22.27 15.85,22.34 16.01,22.34 16.07,22.41 16.07,22.71 16.01,22.77 15.84,22.77 15.78,22.84 15.78,23.29 16.71,24.22 17.04,24.22 17.2,24.07 17.42,24.07 17.58,24.22 17.82,24.22 18,24.04 18,23.8 18.15,23.65 18.39,23.65 18.69,23.35 18.69,23.18 v1(18.49,22.98)
  BOTTOM w0.095: J2.55 18.63,22.12 18.69,22.18 18.69,22.78 v1(18.49,22.98)
DSI_D0_P: length 13.7
  TOP w0.089: U3.C15 15.63,16.7 15.63,18.29 15.75,18.41 15.76,18.41 15.9,18.56 15.9,20.81 15.5,21.22 15.5,21.55
  TOP w0.095: 15.5,21.55 15.5,23.41 16.59,24.5 17.94,24.5 18.97,23.47 18.97,23.18 v1(19.17,22.98)
  BOTTOM w0.095: J2.57 19.03,22.12 18.97,22.18 18.97,22.78 v1(19.17,22.98)
DSI_D1_N: length 13.6
  TOP w0.089: U3.A17 16.88,17.96 17.1,18.18 17.1,18.41 17.17,18.48 17.37,18.48 17.46,18.57 17.46,18.79 17.37,18.88 17.19,18.88 17.1,18.97 17.1,19.31
  TOP w0.095: 17.1,19.31 17.2,19.41 17.2,20.12 17.44,20.36 17.71,20.36 v1(17.91,20.16)
  BOTTOM w0.095: J2.43 16.23,21.24 16.29,21.18 16.29,20.92 15.7,20.34 15.7,19.97 15.49,19.75 15.04,19.75 14.66,19.37 14.66,19.16 14.51,19.01 14.51,18.41 14.77,18.15 15.52,18.15 15.8,18.43 16.54,18.43 17.1,18.99 17.1,20.08 17.38,20.36 17.71,20.36 v1(17.91,20.16)
DSI_D1_P: length 13.7
  TOP w0.089: 16.92,19.52 16.92,19.24 16.92,19.23 16.92,18.9 16.92,18.89 16.92,18.33 16.63,18.04 16.63,17.2 U3.B17
  TOP w0.095: 16.92,19.52 16.92,20.23 17.33,20.64 17.71,20.64 v1(17.91,20.84)
  BOTTOM w0.095: v1(17.91,20.84) 17.71,20.64 17.26,20.64 16.82,20.2 16.82,19.11 16.42,18.71 15.69,18.71 15.41,18.43 14.89,18.43 14.79,18.53 14.79,18.89 14.94,19.04 14.94,19.25 15.16,19.48 15.6,19.48 15.98,19.85 15.98,20.22 16.57,20.81 16.57,21.18 16.63,21.24 J2.45
DSI_LCD_BL_CTRL: length 7.8
  TOP w0.089: v1(20.63,22.34) 20.45,22.17 20.3,22.17 19.18,21.05 19.18,20.69 19,20.51 19,19.78 18.2,18.98 18.2,17.63 18.13,17.56 18.13,16.71 U3.C19
  BOTTOM w0.089: J2.65 v1(20.63,22.34)
DSI_LCD_INT: length 15.7
  TOP w0.089: v1(14.36,22.96) 14.53,22.78 14.53,22.55 15.17,21.91 15.17,21.16 15.68,20.65 15.68,18.66 15.45,18.43 15.45,17.52 U3.A14
  LAYER_3 w0.089: v1(21,23.13) 20.76,23.13 19.77,22.14 15.17,22.14 15.05,22.26 15.05,22.26 14.86,22.44 14.86,22.45 v1(14.36,22.96)
  BOTTOM w0.089: J2.61 19.83,22.31 20.63,23.11 20.73,23.11 20.76,23.13 v1(21,23.13)
DSI_RESET: length 9.4
  TOP w0.089: v2(17.89,15.97) 17.88,15.96 U3.D19
  GND02 w0.089: v2(17.89,15.97) 18.37,16.45 18.37,19.44 19.16,20.23 19.16,21.33 20.63,22.8 20.83,22.8 v1(21,22.62)
  BOTTOM w0.089: v1(21,22.62) 21,22.37 21.03,22.35 J2.67
DSI_TE: length 24.5
  TOP w0.089: U3.AA19 17.88,7.31 18.13,7.06 18.13,5.86 19.13,4.86 19.13,3.7 18.81,3.38 v1(18.57,3.38)
  LAYER_6 w0.089: v1(18.57,3.38) 18.01,3.93 18.01,7.64 18.39,8.02 18.39,18.81 18.39,18.82 18.39,19.38 19.61,20.59 19.69,20.59 v1(19.87,20.77)
  BOTTOM w0.089: v1(19.87,20.77) 20.23,21.13 J2.63
DVP_D0: length 20.9
  TOP w0.089: v1(15.13,17.8) 15.13,17.2 U3.B14
  LAYER_6 w0.089: v1(0.91,11.13) 1.75,11.13 2.84,12.23 2.84,14.95 3.53,15.64 7.68,15.64 8.06,16.02 11.99,16.02 12.22,15.79 12.22,15.61 12.55,15.28 12.87,15.28 15.13,17.55 v1(15.13,17.8)
  BOTTOM w0.089: J1.46 v1(0.91,11.13)
DVP_D1: length 20.8
  TOP w0.089: U3.C2 9.13,16.71 8.78,16.71 7.82,17.67 v1(7.82,17.97)
  LAYER_6 w0.089: v1(0.75,11.57) 1.94,11.57 2.67,12.3 2.67,15.02 3.46,15.81 5.23,15.81 5.32,15.9 5.32,16.13 5.41,16.22 5.58,16.22 5.67,16.13 5.67,15.9 5.76,15.81 5.94,15.81 6.03,15.9 6.03,16.13 6.12,16.22 6.29,16.22 6.38,16.13 6.38,15.9 6.47,15.81 6.65,15.81 6.74,15.9 6.74,16.13 6.83,16.22 7.01,16.22 7.09,16.13 7.09,15.9 7.18,15.81 7.5,15.81 7.93,16.25 9.62,16.25 9.71,16.34 9.71,17.03 9.6,17.14 8.02,17.14 7.82,17.35 v1(7.82,17.97)
  BOTTOM w0.089: v1(0.75,11.57) 0.78,11.57 0.82,11.53 J1.48
DVP_D2: length 20
  GND02 w0.089: v2(10.39,16.45) 10.39,18.31 10.06,18.64 v1(9.81,18.64)
  LAYER_6 w0.089: v1(9.81,18.64) 9.43,18.64 9.35,18.55 9.35,17.53 9.26,17.44 9.08,17.44 8.99,17.53 8.99,18.52 8.88,18.64 7.98,18.64 7.22,17.87 7.22,16.98 6.84,16.6 6.43,16.6 6.35,16.69 6.35,16.84 6.26,16.93 6.08,16.93 5.99,16.84 5.99,16.69 5.9,16.6 5.72,16.6 5.63,16.69 5.63,16.84 5.55,16.93 5.37,16.93 5.28,16.84 5.28,16.69 5.19,16.6 4.7,16.6 4.09,15.99 3.38,15.99 2.49,15.1 2.49,12.37 2.1,11.99 v1(0.92,11.99)
  BOTTOM w0.089: J1.50 1.04,11.93 1.02,11.95 0.95,11.95 v1(0.92,11.99)
DVP_D3: length 19.9
  TOP w0.089: U3.C8 12.63,16.2 12.63,15.67 v1(12.7,15.6)
  LAYER_6 w0.089: v1(12.7,15.6) 12.7,16.33 9.97,19.06 8,19.06 6.23,17.29 5.14,17.29 4.06,16.21 3.3,16.21 3.26,16.17 3.26,16.17 2.31,15.22 2.31,12.71 1.96,12.36 v1(0.67,12.36)
  BOTTOM w0.089: v1(0.67,12.36) 0.78,12.36 0.81,12.33 J1.52
DVP_D4: length 19.9
  TOP w0.089: v1(10.6,20.31) 10.22,19.93 10.22,19.07 10.34,18.94 10.34,17.68 10.38,17.64 U3.A4
  LAYER_6 w0.089: v1(0.96,12.73) 1.82,12.73 1.91,12.82 1.91,16.04 2.44,16.58 3.46,16.58 4.48,17.6 4.61,17.6 4.75,17.46 4.88,17.46 5,17.59 5,17.71 4.86,17.85 4.86,17.98 4.99,18.1 5.11,18.1 5.25,17.96 5.38,17.96 5.5,18.09 5.5,18.21 5.36,18.36 5.36,18.48 5.49,18.61 5.61,18.61 5.76,18.47 5.88,18.47 6.01,18.59 6.01,18.72 5.87,18.86 5.87,18.98 6.2,19.32 9.3,19.32 9.66,19.68 10.12,19.68 10.42,19.98 10.42,20.14 v1(10.6,20.31)
  BOTTOM w0.089: J1.54 v1(0.96,12.73)
DVP_D5: length 26.2
  TOP w0.089: U3.D14 v2(15.4,15.97)
  GND02 w0.089: v1(15.33,20.07) 15.05,19.78 15.05,18.82 14.81,18.58 14.81,17.53 15.19,17.15 15.19,16.17 v2(15.4,15.97)
  LAYER_6 w0.089: v1(15.33,20.07) 13.99,20.07 13.8,19.88 13.8,19.41 13.44,19.06 12.74,19.06 11.13,20.67 10.44,20.67 10.29,20.51 10.29,20.25 9.91,19.88 9.53,19.88 9.17,19.52 6.15,19.52 3.39,16.75 2.37,16.75 1.73,16.12 1.73,13.43 1.44,13.13 v1(0.68,13.13)
  BOTTOM w0.089: J1.56 v1(0.68,13.13)
DVP_D6: length 19.8
  TOP w0.089: v1(9.32,20.37) 9.32,20.08 9.47,19.93 9.47,18.19 9.88,17.77 U3.A3
  LAYER_6 w0.089: v1(0.96,13.53) 1.36,13.53 1.55,13.73 1.55,16.25 2.24,16.93 3.31,16.93 5.77,19.39 5.77,19.85 6.13,20.21 6.74,20.21 6.81,20.13 6.81,19.8 6.91,19.7 7.5,19.7 7.59,19.79 7.59,20.32 7.68,20.41 8.49,20.41 8.58,20.32 8.58,20.15 8.49,20.06 8.03,20.06 7.94,19.97 7.94,19.79 8.03,19.7 9.1,19.7 9.32,19.92 v1(9.32,20.37)
  BOTTOM w0.089: J1.58 v1(0.96,13.53)
DVP_D7: length 21.8
  TOP w0.089: v1(13.31,19.85) 13.63,19.54 13.63,17.21 U3.B10
  LAYER_6 w0.089: v1(0.67,13.88) 1.07,13.88 1.35,14.16 1.35,15.03 1.36,15.04 1.36,16.3 2.16,17.11 3.24,17.11 5.59,19.46 5.59,19.93 6.06,20.4 6.98,20.4 7.95,21.38 11.23,21.38 12.78,19.83 13.04,19.83 13.07,19.85 v1(13.31,19.85)
  BOTTOM w0.089: v1(0.67,13.88) 0.7,13.91 0.8,13.91 0.82,13.93 J1.60
DVP_HSYNC: length 19.8
  TOP w0.089: U3.V4 10.38,8.95 v2(10.37,8.95)
  GND02 w0.089: v1(7.78,10.21) 8.09,9.9 8.59,9.9 9.2,9.29 10.03,9.29 v2(10.37,8.95)
  LAYER_3 w0.089: v1(0.84,14.32) 1.58,14.32 1.83,14.06 1.83,13.72 1.74,13.63 1.39,13.63 1.3,13.54 1.3,13.37 1.39,13.28 1.74,13.28 1.83,13.19 1.83,13.01 1.74,12.92 1.39,12.92 1.3,12.83 1.3,12.65 1.39,12.57 1.74,12.57 1.83,12.48 1.83,12.3 1.74,12.21 1.39,12.21 1.3,12.12 1.3,11.94 1.39,11.85 1.74,11.85 1.83,11.77 1.83,11.59 1.74,11.5 1.41,11.5 1.33,11.41 1.33,11.23 1.41,11.15 1.74,11.15 1.83,11.06 1.83,10.71 2.01,10.53 3,10.53 3.48,11.01 3.76,11.01 3.92,10.86 4.7,10.86 4.79,10.94 4.79,11.18 4.88,11.27 5.06,11.27 5.15,11.18 5.15,10.94 5.23,10.86 5.41,10.86 5.5,10.94 5.5,11.18 5.59,11.27 5.77,11.27 5.86,11.18 5.86,10.94 5.95,10.86 6.6,10.86 6.74,10.99 7.65,10.99 7.78,10.86 v1(7.78,10.21)
  BOTTOM w0.089: v1(0.84,14.32) 0.86,14.33 J1.62
DVP_PCLK: length 25.3
  TOP w0.089: U3.AC8 12.38,5.72 12.65,5.45 12.65,4.61 12.88,4.38 12.88,4.38 v1(13.06,4.21)
  LAYER_3 w0.089: v1(13.06,4.21) 12.88,4.38 12.88,4.38 12.81,4.46 12.81,5.12 12.27,5.66 10.31,5.66 8.41,7.56 7.62,7.56 7.17,8.02 5.75,8.02 4.45,9.31 3.15,9.31 2.8,9.67 1.76,9.67 1.01,8.93 0.57,8.93 0.36,9.13 0.36,14.78 0.44,14.86 v1(0.44,15.1)
  BOTTOM w0.089: J1.66 0.72,15.13 0.68,15.1 v1(0.44,15.1)
DVP_VSYNC: length 24
  TOP w0.089: U3.D11 v2(13.92,15.95)
  GND02 w0.089: v1(12.96,20.82) 12.2,20.82 11.99,20.62 11.99,17.36 13.4,15.95 v2(13.92,15.95)
  LAYER_6 w0.089: v1(0.87,14.8) 1.18,15.11 1.18,16.43 2.04,17.29 3.16,17.29 5.36,19.49 5.36,19.95 6.01,20.6 6.85,20.6 7.8,21.56 12.73,21.56 12.96,21.33 12.96,21.07 v1(12.96,20.82)
  BOTTOM w0.089: J1.64 0.96,14.73 0.89,14.8 v1(0.87,14.8)
ETH_CLK: length 16.3
  TOP w0.089: U3.AB9 12.88,6.35 12.89,6.33 v1(12.89,5.99)
  LAYER_3 w0.089: v1(0.87,10.28) 1.13,10.28 1.16,10.3 5.7,10.3 6.4,9.6 7.59,9.6 7.71,9.72 8.36,9.72 9.12,8.96 9.12,7.56 10.39,6.29 12.3,6.29 12.6,5.99 v1(12.89,5.99)
  BOTTOM w0.127: J1.42 0.93,10.33 v1(0.87,10.28)
ETH_CLK125: length 20.8
  TOP w0.089: v1(11.75,8.8) 11.43,8.49 11.43,8.22 11.38,8.17 U3.Y6
  BOTTOM w0.127: J1.12 2.01,4.33 3.57,2.77 3.57,1.74 3.79,1.53 5.67,1.53 5.8,1.66 5.8,1.72 5.93,1.84 6.18,1.84 6.31,1.72 6.31,1.66 6.43,1.53 6.69,1.53 6.82,1.66 6.82,1.72 6.94,1.84 7.2,1.84 7.32,1.72 7.32,1.66 7.45,1.53 7.69,1.53 7.82,1.66 7.82,1.77 7.95,1.9 8.2,1.9 8.33,1.77 8.33,1.66 8.45,1.53 8.76,1.53 9.2,1.97 10.9,1.97 11.16,2.23 11.16,5.12 11.54,5.5 11.54,8.16 11.49,8.21 11.49,8.59 11.7,8.8 v1(11.75,8.8)
ETH_GTX_CLK: length 11.7
  TOP w0.089: v1(7.29,5.35) 8.41,5.35 9.13,6.07 9.13,6.7 U3.AB2
  LAYER_3 w0.127: v1(7.29,5.35) 6.58,4.64 5.29,4.64 4.82,5.1 4.14,5.1 4.01,4.98 4.01,4.79 3.89,4.66 3.63,4.66 3.51,4.79 3.51,4.98 3.38,5.1 2.98,5.1 2.8,4.92 v1(2.8,4.28)
  BOTTOM w0.127: v1(2.8,4.28) 2.8,4.97 2.23,5.53 J1.18
ETH_MDC: length 18.8
  TOP w0.089: v1(8.97,2.63) 9.4,2.63 10.22,3.45 10.22,4.28 11.13,5.2 11.13,7.2 U3.AA6
  LAYER_6 w0.127: v1(0.56,8.55) 0.87,8.55 1.25,8.17 1.25,6.59 1.96,5.88 2.09,5.88 5,2.98 8.63,2.98 v1(8.97,2.63)
  BOTTOM w0.127: v1(0.56,8.55) 0.78,8.33 J1.32
ETH_MDINT: length 10.1
  TOP w0.089: U3.V2 8.13,8.95 v1(7.85,8.68)
  LAYER_3 w0.127: v1(7.85,8.68) 5.47,8.68 4.14,10 1.06,10 1.02,9.96 0.98,9.96 v1(0.79,9.77)
  BOTTOM w0.127: v1(0.79,9.77) 0.79,9.81 0.92,9.93 J1.40
ETH_MDIO: length 17.1
  TOP w0.089: U3.AC3 9.88,5.88 8.31,4.31 v1(7.9,4.31)
  LAYER_6 w0.127: v1(1.99,8.63) 2.44,8.17 2.44,5.98 2.65,5.77 2.88,5.77 3.28,6.17 3.46,6.17 3.63,5.99 3.63,5.81 3.22,5.39 3.22,5.21 3.37,5.06 3.58,5.06 3.92,5.4 4.1,5.4 4.28,5.22 4.28,5.04 3.92,4.68 3.92,4.5 4.12,4.31 4.53,4.31 4.66,4.18 4.66,4.08 4.79,3.95 5.04,3.95 5.17,4.08 5.17,4.18 5.3,4.31 5.55,4.31 5.68,4.18 5.68,4.08 5.8,3.95 6.06,3.95 6.19,4.08 6.19,4.18 6.31,4.31 6.57,4.31 6.72,4.16 6.72,3.83 6.85,3.7 7.1,3.7 7.23,3.83 7.23,4.18 7.35,4.31 v1(7.9,4.31)
  BOTTOM w0.127: J1.34 1.88,8.73 v1(1.99,8.63)
ETH_NRST: length 12.7
  TOP w0.089: v1(7.85,5.04) 8.43,5.04 9.38,5.99 U3.AC2
  LAYER_6 w0.127: v1(7.85,5.04) 7.45,5.04 7.41,4.99 6.18,4.99 2.87,8.3 2.87,9.06 2.24,9.69 1.3,9.69 v1(0.84,9.24)
  BOTTOM w0.127: J1.38 1.23,9.53 1.14,9.44 1.05,9.44 v1(0.84,9.24)
ETH_RX_CLK: length 20.9
  TOP w0.089: U3.AA4 v2(10.39,7.45)
  GND02 w0.089: v1(9.7,2.4) 9.7,2.93 10.39,3.62 v2(10.39,7.45)
  LAYER_6 w0.127: v1(1.99,4.73) 2.42,4.3 2.42,3.83 2.54,3.7 2.85,3.7 2.98,3.57 2.98,3.32 2.85,3.19 2.54,3.19 2.42,3.07 2.42,2.81 2.54,2.69 2.85,2.69 2.98,2.56 2.98,2.3 2.85,2.18 2.54,2.18 2.42,2.05 2.42,1.64 2.58,1.48 5.78,1.48 5.91,1.6 5.91,1.79 6.04,1.92 6.29,1.92 6.42,1.79 6.42,1.6 6.54,1.48 6.8,1.48 6.92,1.6 6.92,1.82 7.05,1.95 7.31,1.95 7.43,1.82 7.43,1.6 7.56,1.48 7.81,1.48 7.94,1.6 7.94,1.87 8.07,2 8.32,2 8.45,1.87 8.45,1.6 8.58,1.48 9.36,1.48 9.7,1.81 v1(9.7,2.4)
  BOTTOM w0.127: J1.14 v1(1.99,4.73)
ETH_RX_DV: length 21
  TOP w0.089: U3.AB8 12.13,6.71 12.13,5.51 12.25,5.39 v1(12.25,5.15)
  LAYER_3 w0.127: v1(12.25,5.15) 11.38,5.15 11.23,4.99 11.23,4.07 11.36,3.95 11.82,3.95 11.94,3.82 11.94,3.59 11.82,3.46 10.9,3.46 10.77,3.34 10.77,3.08 10.9,2.96 11.79,2.96 11.94,2.8 11.94,2.55 11.82,2.42 11.36,2.42 11.23,2.3 11.23,2 v1(10.85,1.62)
  BOTTOM w0.127: v1(10.85,1.62) 9.28,1.62 8.97,1.31 3.56,1.31 3.36,1.51 3.36,2.58 2,3.93 J1.10
ETH_RXD0: length 20.9
  TOP w0.089: v1(12.07,4.23) 12.07,4.74 11.88,4.93 U3.AC7
  BOTTOM w0.127: v1(12.07,4.23) 12.07,3.92 12.02,3.86 12.02,1.72 12.15,1.59 13.29,1.59 13.47,1.41 13.47,0.52 13.31,0.37 2.62,0.37 2.11,0.88 2.11,2.1 1.88,2.33 J1.2
ETH_RXD1: length 21
  TOP w0.089: v1(11.73,4.64) 11.73,4.72 11.63,4.82 11.63,6.71 U3.AB7
  BOTTOM w0.127: v1(11.73,4.64) 11.73,1.55 11.97,1.31 13.03,1.31 13.21,1.13 13.21,0.73 13.07,0.59 2.89,0.59 2.44,1.03 2.44,2.15 1.86,2.73 J1.4
ETH_RXD2: length 21
  TOP w0.089: 10.47,3.95 10.47,4.26 11.38,5.17 U3.AB6
  TOP w0.127: 10.47,3.95 10.47,3.04 10.14,2.71 10.14,1.95 9.91,1.72 9.44,1.72 9.31,1.84 9.31,2.05 9.19,2.18 8.93,2.18 8.8,2.05 8.8,1.84 8.68,1.72 8.34,1.72 8.21,1.59 8.21,1.08 8.37,0.92 v1(10.14,0.92)
  BOTTOM w0.127: v1(10.14,0.92) 9.96,0.92 9.87,0.83 3.15,0.83 2.8,1.18 2.8,2.25 1.92,3.13 J1.6
ETH_RXD3: length 21.3
  TOP w0.089: U3.AA7 12.13,7.7 12.13,8.67 12.21,8.75 12.25,8.75 v1(12.43,8.92)
  BOTTOM w0.127: v1(12.43,8.92) 12.24,8.74 12.24,8.71 12.15,8.62 12.15,7.66 11.84,7.36 11.84,5.43 11.38,4.97 11.38,1.67 11,1.29 9.4,1.29 9.17,1.06 3.36,1.06 3.08,1.34 3.08,2.43 1.97,3.53 J1.8
